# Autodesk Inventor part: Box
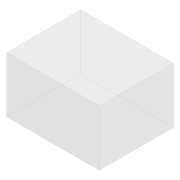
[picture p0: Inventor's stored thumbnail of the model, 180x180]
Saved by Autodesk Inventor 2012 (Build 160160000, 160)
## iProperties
Created: 2011-09
Part Number: Box
Material: Glas
Document SubType Name: Modeling
Designer: Administrator
Density: 2.18 g/cm^3
Mass: 1.0464e+06 g
Surface Area: 37600 cm^2
Volume: 480000 cm^3
Author: Administrator
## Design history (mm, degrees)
sketch "Skizze1"
  geometry: L1 (-500, 400)-(500, 400); L2 (500, 400)-(500, -400); L3 (500, -400)-(-500, -400); L4 (-500, -400)-(-500, 400); 3 further points
  constraints: 8 end point, 2 midpoint, 2 parallel, 1 horizontal, 1 horizontal alignment, 1 perpendicular, 1 vertical alignment
  dimensions: "d0" = 1000 distance of L1.start L1.end; "d1" = 800 distance of L3.end L1.start
extrude "Extrusion1" new body sketch "Skizze1" distance "d2" = 600; taper "d3" = 0 deg
node "Volumenkörper1"
